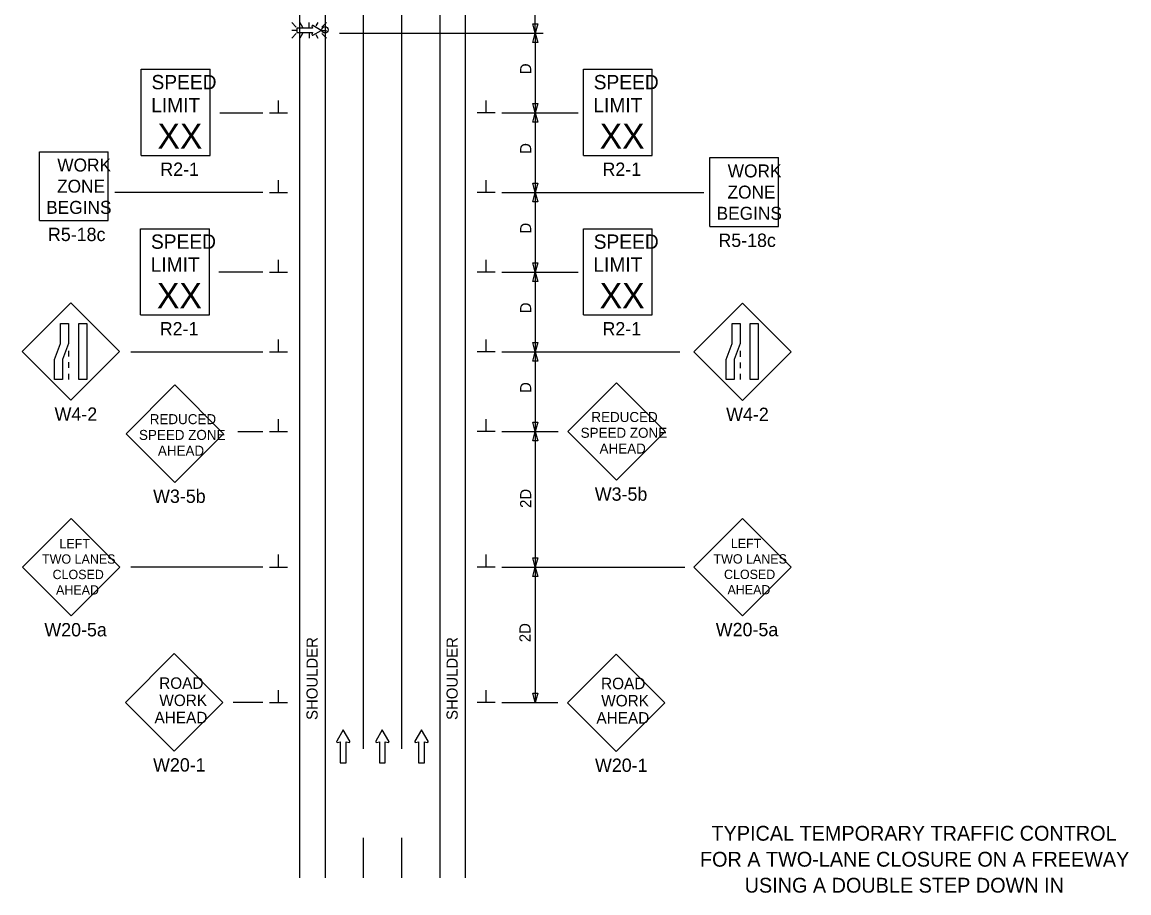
# Model space of a CAD drawing. Extents: x 16732 to 18478, y 5523 to 6928.
# Drawn here: x 16743 to 17437, y 5993 to 6540 of the extents above; entities that cross this region are included whole.
import ezdxf

# ---------------------------------------------------------------- set-up
doc = ezdxf.new("R2010")
doc.units = 0
for name, color, linetype in [('ALI_LEGAL_EX', 7, 'Continuous'), ('BORDER', 7, 'Continuous'), ('MT_SCRATCH_LEVEL_E', 7, 'Continuous'), ('PAVT_EDGE_EX', 7, 'Continuous'), ('TRAFFIC_SIGNS_PR', 7, 'Continuous'), ('TYPICAL_TEXT_DIMEN_PR', 7, 'Continuous')]:
    doc.layers.add(name, color=color, linetype=linetype)

msp = doc.modelspace()

# ---------------------------------------------------------------- linework, layer by layer
at = {"layer": 'ALI_LEGAL_EX'}
for p, q in [((16956.63, 6927.83), (16956.63, 6083.69)), ((16980.63, 6927.83), (16980.63, 6083.69))]:
    msp.add_line(p, q, dxfattribs=at)
for points in [[(16956.63, 6527.83), (16956.63, 6502.83)], [(16980.63, 6527.83), (16980.63, 6502.83)], [(16956.63, 6427.83), (16956.63, 6402.83)], [(16980.63, 6427.83), (16980.63, 6402.83)], [(16956.63, 6327.83), (16956.63, 6302.83)], [(16980.63, 6327.83), (16980.63, 6302.83)], [(16956.63, 6227.83), (16956.63, 6202.83)], [(16980.63, 6227.83), (16980.63, 6202.83)], [(16956.63, 6127.83), (16956.63, 6102.83)], [(16980.63, 6127.83), (16980.63, 6102.83)], [(16956.63, 6027.83), (16956.63, 6002.83)], [(16980.63, 6027.83), (16980.63, 6002.83)]]:
    msp.add_lwpolyline(points, dxfattribs=at)
at = {"layer": 'MT_SCRATCH_LEVEL_E'}
for p, q in [((16944.07, 6095.7), (16939.96, 6088.46)), ((16948.22, 6088.46), (16944.07, 6095.7)), ((16968.6, 6095.7), (16964.49, 6088.46)), ((16972.75, 6088.46), (16968.6, 6095.7)), ((16993.16, 6095.7), (16989.05, 6088.46)), ((16997.31, 6088.46), (16993.16, 6095.7)), ((16940.44, 6087.78), (16942.22, 6088.09)), ((16942.22, 6088.09), (16942.22, 6074.84)), ((16945.96, 6074.84), (16945.96, 6088.09)), ((16945.96, 6088.09), (16947.74, 6087.78)), ((16964.97, 6087.78), (16966.75, 6088.09)), ((16966.75, 6088.09), (16966.75, 6074.84)), ((16970.49, 6074.84), (16970.49, 6088.09)), ((16970.49, 6088.09), (16972.27, 6087.78)), ((16989.53, 6087.78), (16991.31, 6088.09)), ((16991.31, 6088.09), (16991.31, 6074.84)), ((16995.05, 6074.84), (16995.05, 6088.09)), ((16995.05, 6088.09), (16996.83, 6087.78)), ((16942.22, 6074.84), (16945.96, 6074.84)), ((16966.75, 6074.84), (16970.49, 6074.84)), ((16991.31, 6074.84), (16995.05, 6074.84))]:
    msp.add_line(p, q, dxfattribs=at)
for centre, start, end in [((16940.37, 6088.24), 150.42484, 279.96381), ((16947.81, 6088.24), 260.03619, 29.77312), ((16964.9, 6088.24), 150.42484, 279.96381), ((16972.34, 6088.24), 260.03619, 29.77312), ((16989.46, 6088.24), 150.42484, 279.96381), ((16996.9, 6088.24), 260.03619, 29.77312)]:
    msp.add_arc(centre, 0.463, start, end, dxfattribs=at)
at = {"layer": 'PAVT_EDGE_EX'}
for p, q in [((16916.63, 6919.19), (16916.63, 6002.83)), ((16932.63, 6919.19), (16932.63, 6002.83)), ((17004.63, 6919.19), (17004.63, 6002.83)), ((17020.63, 6919.19), (17020.63, 6002.83))]:
    msp.add_line(p, q, dxfattribs=at)
at = {"layer": 'TRAFFIC_SIGNS_PR'}
for p, q in [((16914.54, 6536.48), (16911.72, 6539.3)), ((16916.83, 6539.3), (16918.46, 6536.48)), ((16922.62, 6536.48), (16922.62, 6539.3)), ((16928.09, 6539.3), (16926.88, 6537.2)), ((16933.53, 6539.29), (16930.71, 6536.48)), ((16914.54, 6534.44), (16911.72, 6534.44)), ((16914.54, 6532.41), (16911.72, 6529.59)), ((16918.49, 6532.41), (16916.86, 6529.59)), ((16922.62, 6532.41), (16922.62, 6529.59)), ((16926.8, 6531.78), (16928.06, 6529.59)), ((16930.71, 6534.44), (16933.53, 6534.44)), ((16933.53, 6529.59), (16930.71, 6532.41)), ((16817.24, 6510.02), (16860.44, 6510.02)), ((16817.24, 6456.02), (16817.24, 6510.02)), ((16860.44, 6456.02), (16860.44, 6510.02)), ((17094.79, 6510.02), (17137.99, 6510.02)), ((17094.79, 6456.02), (17094.79, 6510.02)), ((17137.99, 6456.02), (17137.99, 6510.02)), ((16753.32, 6415.13), (16753.32, 6458.33)), ((16753.32, 6458.33), (16796.52, 6458.33)), ((16796.52, 6415.13), (16796.52, 6458.33)), ((16817.24, 6456.02), (16860.44, 6456.02)), ((17094.79, 6456.02), (17137.99, 6456.02)), ((17174.14, 6411.43), (17174.14, 6454.63)), ((17174.14, 6454.63), (17217.34, 6454.63)), ((17217.34, 6411.43), (17217.34, 6454.63)), ((16753.32, 6415.13), (16796.52, 6415.13)), ((16816.9, 6409.93), (16860.1, 6409.93)), ((16816.9, 6355.93), (16816.9, 6409.93)), ((16860.1, 6355.93), (16860.1, 6409.93)), ((17094.79, 6409.93), (17137.99, 6409.93)), ((17094.79, 6355.93), (17094.79, 6409.93)), ((17137.99, 6355.93), (17137.99, 6409.93)), ((17174.14, 6411.43), (17217.34, 6411.43)), ((16773.06, 6363.46), (16742.52, 6332.91)), ((16803.61, 6332.91), (16773.06, 6363.46)), ((17194.59, 6363.33), (17164.04, 6332.79)), ((17225.14, 6332.79), (17194.59, 6363.33)), ((16816.9, 6355.93), (16860.1, 6355.93)), ((17094.79, 6355.93), (17137.99, 6355.93)), ((16742.52, 6332.91), (16773.06, 6302.36)), ((16771.66, 6333.46), (16771.66, 6329.86)), ((16773.06, 6302.36), (16803.61, 6332.91)), ((17164.04, 6332.79), (17194.59, 6302.24)), ((17193.19, 6333.34), (17193.19, 6329.74)), ((17194.59, 6302.24), (17225.14, 6332.79)), ((16771.66, 6326.26), (16771.66, 6322.66)), ((17193.19, 6326.14), (17193.19, 6322.54)), ((16771.66, 6319.06), (16771.66, 6315.46)), ((17193.19, 6318.94), (17193.19, 6315.34)), ((16838.3, 6311.97), (16807.75, 6281.42)), ((16868.84, 6281.42), (16838.3, 6311.97)), ((17115.52, 6313.31), (17084.97, 6282.76)), ((17146.07, 6282.76), (17115.52, 6313.31)), ((16807.75, 6281.42), (16838.3, 6250.88)), ((16838.3, 6250.88), (16868.84, 6281.42)), ((17084.97, 6282.76), (17115.52, 6252.22)), ((17115.52, 6252.22), (17146.07, 6282.76)), ((16773.19, 6228.21), (16742.65, 6197.67)), ((16803.74, 6197.67), (16773.19, 6228.21)), ((17194.64, 6228.31), (17164.09, 6197.76)), ((17225.19, 6197.76), (17194.64, 6228.31)), ((16742.65, 6197.67), (16773.19, 6167.12)), ((16773.19, 6167.12), (16803.74, 6197.67)), ((17164.09, 6197.76), (17194.64, 6167.21)), ((17194.64, 6167.21), (17225.19, 6197.76)), ((16838.03, 6143.41), (16807.48, 6112.86)), ((16868.58, 6112.86), (16838.03, 6143.41)), ((17115.41, 6143.19), (17084.87, 6112.64)), ((17145.96, 6112.64), (17115.41, 6143.19)), ((16807.48, 6112.86), (16838.03, 6082.31)), ((16838.03, 6082.31), (16868.58, 6112.86)), ((17084.87, 6112.64), (17115.41, 6082.09)), ((17115.41, 6082.09), (17145.96, 6112.64))]:
    msp.add_line(p, q, dxfattribs=at)
for points in [[(16924.45, 6537.12), (16924.68, 6535.83), (16914.96, 6535.83), (16914.96, 6533.09), (16924.68, 6533.09), (16924.45, 6531.78)], [(16924.95, 6531.43), (16930.26, 6534.44), (16924.95, 6537.48)]]:
    msp.add_lwpolyline(points, dxfattribs=at)
for points in [[(16771.66, 6350.61), (16771.66, 6338.03), (16767.9, 6328.04), (16767.9, 6315.46), (16762.84, 6315.46), (16762.84, 6328.04), (16766.61, 6338.03), (16766.61, 6350.61)], [(16783.06, 6350.61), (16783.06, 6315.46), (16778.01, 6315.46), (16778.01, 6350.61)], [(17193.19, 6350.49), (17193.19, 6337.91), (17189.42, 6327.92), (17189.42, 6315.34), (17184.37, 6315.34), (17184.37, 6327.92), (17188.13, 6337.91), (17188.13, 6350.49)], [(17204.59, 6350.49), (17204.59, 6315.34), (17199.54, 6315.34), (17199.54, 6350.49)]]:
    msp.add_lwpolyline(points, close=True, dxfattribs=at)
msp.add_circle((16932.64, 6534.81), 2, dxfattribs=at)
for centre, start, end in [((16924.78, 6537.18), 61.48329, 189.95933), ((16924.78, 6531.73), 170.73078, 298.89165)]:
    msp.add_arc(centre, 0.341, start, end, dxfattribs=at)
at = {"layer": 'TYPICAL_TEXT_DIMEN_PR'}
for p, q in [((17064.63, 6532.76), (17064.63, 6563.32)), ((17064.63, 6532.76), (17063.06, 6538.62)), ((17063.06, 6538.62), (17064.63, 6538.62)), ((17064.63, 6538.62), (17066.2, 6538.62)), ((17066.2, 6538.62), (17064.63, 6532.76)), ((16941.8, 6532.76), (17069.63, 6532.76)), ((17063.06, 6526.9), (17064.63, 6532.76)), ((17064.63, 6532.76), (17064.63, 6482.76)), ((17064.63, 6532.76), (17066.2, 6526.9)), ((17064.63, 6526.9), (17063.06, 6526.9)), ((17066.2, 6526.9), (17064.63, 6526.9)), ((16903.51, 6482.76), (16903.51, 6490.55)), ((17033.76, 6482.76), (17033.76, 6490.55)), ((17064.63, 6482.76), (17063.06, 6488.62)), ((17063.06, 6488.62), (17064.63, 6488.62)), ((17064.63, 6488.62), (17066.2, 6488.62)), ((17066.2, 6488.62), (17064.63, 6482.76)), ((16866.65, 6482.76), (16893.63, 6482.76)), ((16897.88, 6482.76), (16909.13, 6482.76)), ((17039.38, 6482.76), (17028.13, 6482.76)), ((17043.63, 6482.76), (17091.44, 6482.76)), ((17063.06, 6476.9), (17064.63, 6482.76)), ((17064.63, 6482.76), (17064.63, 6432.76)), ((17064.63, 6482.76), (17066.2, 6476.9)), ((17064.63, 6476.9), (17063.06, 6476.9)), ((17066.2, 6476.9), (17064.63, 6476.9)), ((16903.51, 6432.76), (16903.51, 6440.55)), ((17033.76, 6432.76), (17033.76, 6440.55)), ((16893.63, 6432.76), (16800.7, 6432.76)), ((16897.88, 6432.76), (16909.13, 6432.76)), ((17039.38, 6432.76), (17028.13, 6432.76)), ((17043.63, 6432.76), (17170.32, 6432.76)), ((17064.63, 6432.76), (17063.06, 6438.62)), ((17063.06, 6438.62), (17064.63, 6438.62)), ((17063.06, 6426.9), (17064.63, 6432.76)), ((17064.63, 6438.62), (17066.2, 6438.62)), ((17066.2, 6438.62), (17064.63, 6432.76)), ((17064.63, 6432.76), (17066.2, 6426.9)), ((17064.63, 6432.76), (17064.63, 6382.76)), ((17064.63, 6426.9), (17063.06, 6426.9)), ((17066.2, 6426.9), (17064.63, 6426.9)), ((16903.51, 6382.76), (16903.51, 6390.55)), ((17033.76, 6382.76), (17033.76, 6390.55)), ((17064.63, 6382.76), (17063.06, 6388.62)), ((17063.06, 6388.62), (17064.63, 6388.62)), ((17064.63, 6388.62), (17066.2, 6388.62)), ((17066.2, 6388.62), (17064.63, 6382.76)), ((16893.63, 6382.76), (16866.02, 6382.76)), ((16897.88, 6382.76), (16909.13, 6382.76)), ((17039.38, 6382.76), (17028.13, 6382.76)), ((17043.63, 6382.76), (17091.44, 6382.76)), ((17063.06, 6376.9), (17064.63, 6382.76)), ((17064.63, 6382.76), (17064.63, 6332.76)), ((17064.63, 6382.76), (17066.2, 6376.9)), ((17064.63, 6376.9), (17063.06, 6376.9)), ((17066.2, 6376.9), (17064.63, 6376.9)), ((16903.51, 6332.76), (16903.51, 6340.55)), ((17033.76, 6332.76), (17033.76, 6340.55)), ((17064.63, 6332.76), (17063.06, 6338.62)), ((17063.06, 6338.62), (17064.63, 6338.62)), ((17064.63, 6338.62), (17066.2, 6338.62)), ((17066.2, 6338.62), (17064.63, 6332.76)), ((16810.84, 6332.76), (16893.63, 6332.76)), ((16897.88, 6332.76), (16909.13, 6332.76)), ((17039.38, 6332.76), (17028.13, 6332.76)), ((17043.63, 6332.76), (17155.35, 6332.76)), ((17063.06, 6326.9), (17064.63, 6332.76)), ((17064.63, 6332.76), (17066.2, 6326.9)), ((17064.63, 6332.76), (17064.63, 6282.76)), ((17064.63, 6326.9), (17063.06, 6326.9)), ((17066.2, 6326.9), (17064.63, 6326.9)), ((16903.51, 6282.76), (16903.51, 6290.55)), ((17033.76, 6282.76), (17033.76, 6290.55)), ((17064.63, 6282.76), (17063.06, 6288.62)), ((17063.06, 6288.62), (17064.63, 6288.62)), ((17064.63, 6288.62), (17066.2, 6288.62)), ((17066.2, 6288.62), (17064.63, 6282.76)), ((16877.95, 6282.76), (16893.63, 6282.76)), ((16897.88, 6282.76), (16909.13, 6282.76)), ((17039.38, 6282.76), (17028.13, 6282.76)), ((17043.63, 6282.76), (17078.88, 6282.76)), ((17063.06, 6276.9), (17064.63, 6282.76)), ((17064.63, 6282.76), (17064.63, 6197.76)), ((17064.63, 6282.76), (17066.2, 6276.9)), ((17064.63, 6276.9), (17063.06, 6276.9)), ((17066.2, 6276.9), (17064.63, 6276.9)), ((16903.51, 6197.76), (16903.51, 6205.55)), ((17033.76, 6197.76), (17033.76, 6205.55)), ((17064.63, 6197.76), (17063.06, 6203.62)), ((17063.06, 6203.62), (17064.63, 6203.62)), ((17064.63, 6203.62), (17066.2, 6203.62)), ((17066.2, 6203.62), (17064.63, 6197.76)), ((16893.63, 6197.76), (16810.84, 6197.76)), ((16897.88, 6197.76), (16909.13, 6197.76)), ((17039.38, 6197.76), (17028.13, 6197.76)), ((17043.63, 6197.76), (17158.39, 6197.76)), ((17063.06, 6191.9), (17064.63, 6197.76)), ((17064.63, 6197.76), (17064.63, 6112.76)), ((17064.63, 6197.76), (17066.2, 6191.9)), ((17064.63, 6191.9), (17063.06, 6191.9)), ((17066.2, 6191.9), (17064.63, 6191.9)), ((16903.51, 6112.76), (16903.51, 6120.55)), ((17033.76, 6112.76), (17033.76, 6120.55)), ((17064.63, 6112.76), (17063.06, 6118.62)), ((17063.06, 6118.62), (17064.63, 6118.62)), ((17064.63, 6118.62), (17066.2, 6118.62)), ((17066.2, 6118.62), (17064.63, 6112.76)), ((16893.63, 6112.76), (16874.92, 6112.76)), ((16897.88, 6112.76), (16909.13, 6112.76)), ((17039.38, 6112.76), (17028.13, 6112.76)), ((17043.63, 6112.76), (17078.7, 6112.76))]:
    msp.add_line(p, q, dxfattribs=at)

# ---------------------------------------------------------------- texts
at = {"layer": 'BORDER'}
for s, p in [('TYPICAL TEMPORARY TRAFFIC CONTROL', (17175.21, 6026.08)), ('FOR A TWO-LANE CLOSURE ON A FREEWAY', (17167.99, 6009.78)), ('USING A DOUBLE STEP DOWN IN', (17196.04, 5993.48))]:
    msp.add_text(s, height=9.3, dxfattribs=at).set_placement(p)
at = {"layer": 'TRAFFIC_SIGNS_PR'}
for s, height, p in [('SPEED', 9, (16823.73, 6497.48)), ('SPEED', 9, (17101.27, 6497.48)), ('LIMIT', 9, (16823.55, 6483.08)), ('LIMIT', 9, (17101.09, 6483.08)), ('XX', 15.785, (16827.49, 6460.24)), ('XX', 15.785, (17105.04, 6460.24)), ('WORK', 8.119, (16764.57, 6445.92)), ('R2-1', 8.37, (16829.25, 6443.15)), ('R2-1', 8.37, (17106.8, 6443.15)), ('WORK', 8.119, (17185.39, 6442.22)), ('ZONE', 8.119, (16764.43, 6432.64)), ('ZONE', 8.119, (17185.26, 6428.93)), ('BEGINS', 8.119, (16757.6, 6419.35)), ('BEGINS', 8.119, (17178.42, 6415.65)), ('R5-18c', 8.37, (16758.73, 6402.26)), ('SPEED', 9, (16823.39, 6397.4)), ('SPEED', 9, (17101.27, 6397.4)), ('R5-18c', 8.37, (17179.55, 6398.56)), ('LIMIT', 9, (16823.21, 6383)), ('LIMIT', 9, (17101.09, 6383)), ('XX', 15.785, (16827.15, 6360.16)), ('XX', 15.785, (17105.04, 6360.16)), ('R2-1', 8.37, (16828.91, 6343.06)), ('R2-1', 8.37, (17106.8, 6343.06)), ('W4-2', 8.37, (16762.89, 6289.49)), ('REDUCED', 6.3, (17099.83, 6288.74)), ('W4-2', 8.37, (17184.42, 6289.37)), ('REDUCED', 6.3, (16822.61, 6287.39)), ('SPEED ZONE', 6.3, (16815.85, 6277.49)), ('SPEED ZONE', 6.3, (17093.08, 6278.84)), ('AHEAD', 6.3, (16827.73, 6267.59)), ('AHEAD', 6.3, (17104.96, 6268.94)), ('W3-5b', 8.37, (16824.74, 6238.01)), ('W3-5b', 8.37, (17101.97, 6239.35)), ('LEFT', 5.85, (16765.92, 6209.52)), ('LEFT', 5.85, (17187.37, 6209.61)), ('TWO LANES', 5.85, (16755.04, 6199.85)), ('TWO LANES', 5.85, (17176.48, 6199.94)), ('CLOSED', 5.85, (16761.62, 6190.17)), ('CLOSED', 5.85, (17183.07, 6190.26)), ('AHEAD', 5.85, (16763.81, 6180.49)), ('AHEAD', 5.85, (17185.26, 6180.59)), ('W20-5a', 8.37, (16756.48, 6154.25)), ('W20-5a', 8.37, (17177.92, 6154.35)), ('ROAD', 7.2, (16828.52, 6121.34)), ('ROAD', 7.2, (17105.9, 6121.12)), ('WORK', 7.2, (16828.64, 6110.54)), ('WORK', 7.2, (17106.02, 6110.32)), ('AHEAD', 7.2, (16825.61, 6099.74)), ('AHEAD', 7.2, (17102.99, 6099.52)), ('W20-1', 8.37, (16824.72, 6069.44)), ('W20-1', 8.37, (17102.1, 6069.22))]:
    msp.add_text(s, height=height, dxfattribs=at).set_placement(p)
at = {"layer": 'TYPICAL_TEXT_DIMEN_PR'}
for s, p in [('D', (17062.08, 6506.98)), ('D', (17062.08, 6456.98)), ('D', (17062.08, 6406.98)), ('D', (17062.08, 6356.98)), ('D', (17062.08, 6306.98)), ('2D', (17062.08, 6234.83)), ('2D', (17061.64, 6150.62)), ('SHOULDER', (16928.01, 6101.81)), ('SHOULDER', (17015.91, 6101.81))]:
    msp.add_text(s, height=7, rotation=90, dxfattribs=at).set_placement(p)

doc.saveas('drawing.dxf')
